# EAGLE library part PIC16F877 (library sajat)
MICROCONTROLLER
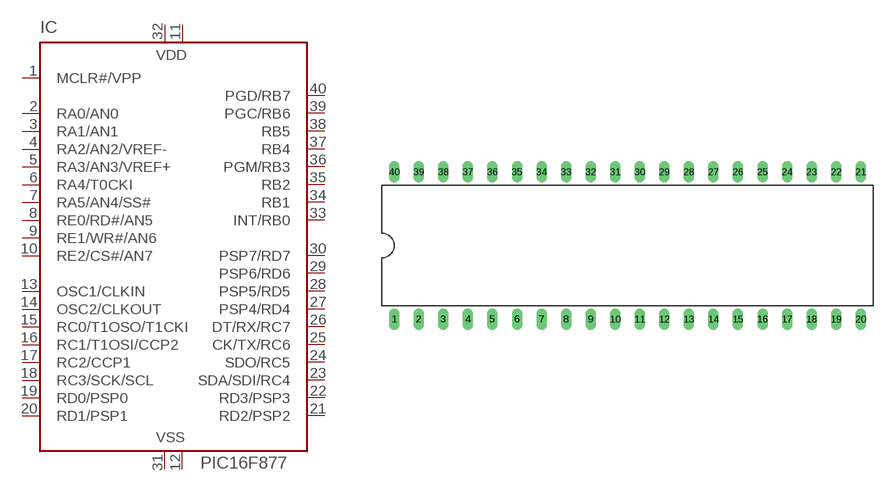
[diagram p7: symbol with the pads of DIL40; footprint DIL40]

Designator prefix IC

## PIC16F8774P, PIC16F8777P  [DIL40]
1  MCLR#/VPP  in
2  RA0/AN0
3  RA1/AN1
4  RA2/AN2/VREF-
5  RA3/AN3/VREF+
6  RA4/T0CKI
7  RA5/AN4/SS#
8  RE0/RD#/AN5
9  RE1/WR#/AN6
10  RE2/CS#/AN7
11  VDD  pwr
12  VSS  pwr
13  OSC1/CLKIN  in
14  OSC2/CLKOUT  out
15  RC0/T1OSO/T1CKI
16  RC1/T1OSI/CCP2
17  RC2/CCP1
18  RC3/SCK/SCL
19  RD0/PSP0
20  RD1/PSP1
21  RD2/PSP2
22  RD3/PSP3
23  SDA/SDI/RC4
24  SDO/RC5
25  CK/TX/RC6
26  DT/RX/RC7
27  PSP4/RD4
28  PSP5/RD5
29  PSP6/RD6
30  PSP7/RD7
31  VSS  pwr
32  VDD  pwr
33  INT/RB0
34  RB1
35  RB2
36  PGM/RB3
37  RB4
38  RB5
39  PGC/RB6
40  PGD/RB7

## Footprint DIL40 (pad centres in mm)
Dual In Line package type P
drill 0.6 pad 1.016 long: 1 -24.13,-7.62; 2 -21.59,-7.62; 3 -19.05,-7.62; 4 -16.51,-7.62; 5 -13.97,-7.62; 6 -11.43,-7.62; 7 -8.89,-7.62; 8 -6.35,-7.62; 9 -3.81,-7.62; 10 -1.27,-7.62; 11 1.27,-7.62; 12 3.81,-7.62; 13 6.35,-7.62; 14 8.89,-7.62; 15 11.43,-7.62; 16 13.97,-7.62; 17 16.51,-7.62; 18 19.05,-7.62; 19 21.59,-7.62; 20 24.13,-7.62; 21 24.13,7.62; 22 21.59,7.62; 23 19.05,7.62; 24 16.51,7.62; 25 13.97,7.62; 26 11.43,7.62; 27 8.89,7.62; 28 6.35,7.62; 29 3.81,7.62; 30 1.27,7.62; 31 -1.27,7.62; 32 -3.81,7.62; 33 -6.35,7.62; 34 -8.89,7.62; 35 -11.43,7.62; 36 -13.97,7.62; 37 -16.51,7.62; 38 -19.05,7.62; 39 -21.59,7.62; 40 -24.13,7.62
